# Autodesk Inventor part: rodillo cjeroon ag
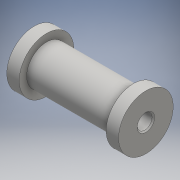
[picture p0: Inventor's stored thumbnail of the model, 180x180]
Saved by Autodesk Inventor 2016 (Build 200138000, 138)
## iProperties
Created: 2016-06
Part Number: rodillo cjeroon ag
Material: Genérico
Document SubType Name: Modeling
Designer: adm
Density: 1 g/cm^3
Appearance: Valor por defecto
Author: adm
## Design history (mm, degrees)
sketch "Boceto1"
  geometry: L1 (0, 0)-(0, 11); L2 (0, 11)-(5, 11); L3 (5, 11)-(5, 8); L4 (5, 8)-(40, 8); L5 (40, 8)-(40, 11); L6 (40, 11)-(45, 11); L7 (0, 0)-(45, 0); L8 (45, 0)-(45, 11)
  constraints: 16 end point, 5 perpendicular, 2 vertical, 1 horizontal, 1 horizontal alignment
  dimensions: "d0" = 45 distance of L1.start L7.end; "d1" = 5 distance of L1.end L2.end; "d2" = 5 distance of L5.end L6.end; "d3" = 11 distance between parallel lines of L7 L2; "d4" = 8 distance between parallel lines of L7 L4
revolve "Revolución1" sketch "Boceto1" stored, may be unused: angle "d5" = 90 deg
sketch "Boceto2"
  geometry: C1 r 3 at (0, 0); 1 further point
  constraints: 1 centre point, 1 coincident
  dimensions: "d6" = 6 diameter of C1
extrude "Extrusión1" cut sketch "Boceto2" stored distance "d7" = 10; taper "d8" = 0 deg
node "Plano de trabajo1"
sketch "Boceto3"
  geometry: L1 (0, 11)-(0, -11) reference; L2 (-45, 11)-(-45, -11) reference; C1 r 1 at (-35, 0); C2 r 1 at (-10, 0); 1 further point
  constraints: 2 centre point
  dimensions: "d10" = 2 diameter of C1; "d11" = 2 diameter of C2; "d12" = 10 distance from line of C2.centre L1; "d13" = 10 distance from line of L2 C1.centre
extrude "Extrusión2" cut sketch "Boceto3" distance "d14" = 10; taper "d15" = 0 deg
chamfer "Chaflán1" distance "d16" = 0.5; stored, may be unused: second distance "d17" = 2, angle "d18" = 45 deg
node "Sólido1"
other parameters: "d9" = 9
